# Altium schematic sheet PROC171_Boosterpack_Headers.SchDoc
size 431 x 279 mm; Date: Not shown in title block; ApprovedBy: Not shown in title block; CheckedBy: Not shown in title block; Author: Not shown in title block; CompanyName: Not shown in title block; Engineer: Not shown in title block; Organization: Not shown in title block; Address1: Not shown in title block; Address2: Not shown in title block; Address3: Not shown in title block; Address4: Not shown in title block; DocumentNumber: 21; Revision: Use project parameter SCH_Rev; SheetNumber: 21; SheetTotal: 27; PageSetup: Record=PageOptions¦CenterHorizontal=True¦CenterVertical=True¦PrintScale=1.00¦XCorrection=1.00¦YCorrection=1.00¦PrintKind=0¦BorderSize=5000000¦LeftOffset=0¦BottomOffset=0¦Orientation=2¦PaperLength=1000¦PaperWidth=1000¦Scale=100¦PaperSource=15¦PrintQuality=600¦MediaType=1¦DitherType=10¦PaperKind=Letter¦PrintScaleMode=1
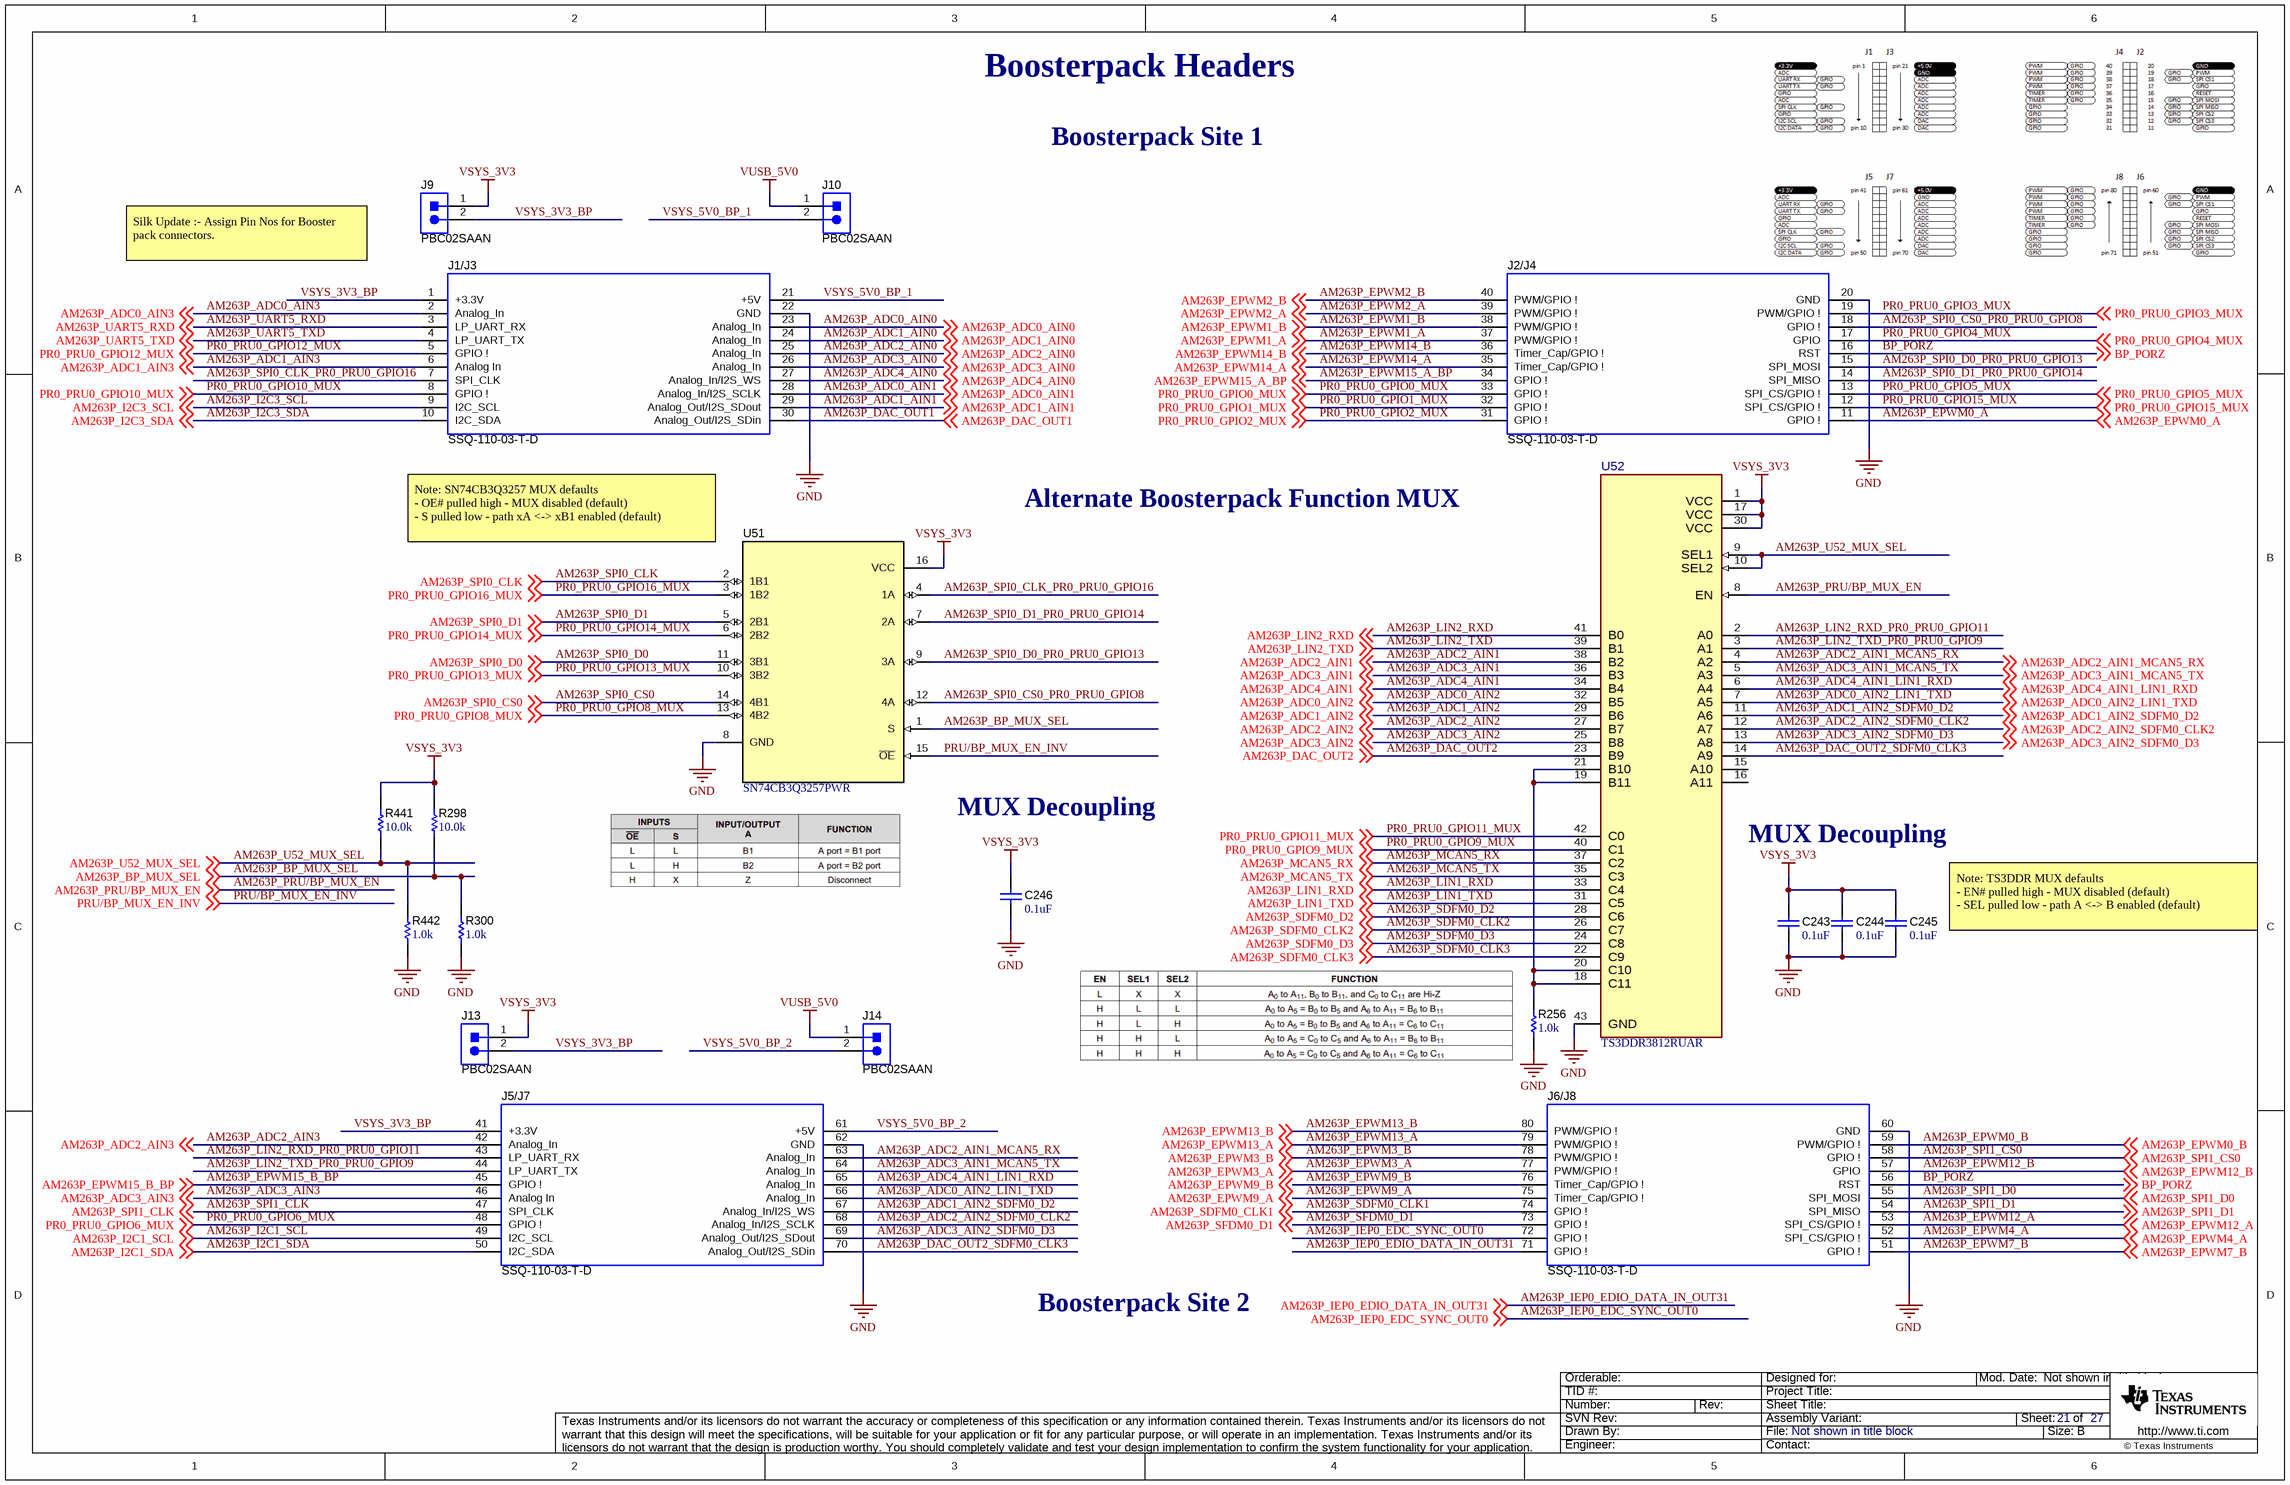
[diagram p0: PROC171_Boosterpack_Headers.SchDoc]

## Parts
C243  ValueDisplayed: 0.1uF  [0402]  (hidden comment: GRM155R71E104KE14D)
C244  ValueDisplayed: 0.1uF  [0402]  (hidden comment: GRM155R71E104KE14D)
C245  ValueDisplayed: 0.1uF  [0402]  (hidden comment: GRM155R71E104KE14D)
C246  ValueDisplayed: 0.1uF  [0402]  (hidden comment: GRM155R71E104KE14D)
J1/J3  SSQ-110-03-T-D  [BoosterPack_40pin_J1J3]
J2/J4  SSQ-110-03-T-D  [BoosterPack_40pin_J2J4]
J5/J7  SSQ-110-03-T-D  [BoosterPack_40pin_J5J7]
J6/J8  SSQ-110-03-T-D  [BoosterPack_40pin_J6J8]
J9  PBC02SAAN  [Sullins_PBC02SAAN]
J10  PBC02SAAN  [Sullins_PBC02SAAN]
J13  PBC02SAAN  [Sullins_PBC02SAAN]
J14  PBC02SAAN  [Sullins_PBC02SAAN]
R256  ValueDisplayed: 1.0k  [0402]  (hidden comment: ERJ-2GEJ102X)
R298  ValueDisplayed: 10.0k  [0402]  (hidden comment: ERJ-2RKF1002X)
R300  ValueDisplayed: 1.0k  [0402]  (hidden comment: ERJ-2GEJ102X)
R441  ValueDisplayed: 10.0k  [0402]  (hidden comment: ERJ-2RKF1002X)
R442  ValueDisplayed: 1.0k  [0402]  (hidden comment: ERJ-2GEJ102X)
U51  SN74CB3Q3257PWR  [PW0016A_L]
U52  TS3DDR3812RUAR  [RUA0042A-MFG]

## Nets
GND: C243.1 C244.1 C245.1 C246.1 J1/J3.22(GND) J2/J4.20(GND) J5/J7.62(GND) J6/J8.60(GND) R256.1 R300.1 R442.1 U51.8(GND) U52.43(GND)
VSYS_3V3: C243.2 C244.2 C245.2 C246.2 J9.1 J13.1 R298.1 R441.1 U51.16(VCC) U52.1(VCC) U52.17(VCC) U52.30(VCC)
VUSB_5V0: J10.1 J14.1
AM263P_ADC0_AIN0: J1/J3.23(Analog_In) ; off-sheet AM263P_ADC0_AIN0
AM263P_ADC0_AIN1: J1/J3.28(Analog_In/I2S_SCLK) ; off-sheet AM263P_ADC0_AIN1
AM263P_ADC0_AIN2: U52.32(B5) ; off-sheet AM263P_ADC0_AIN2
AM263P_ADC0_AIN2_LIN1_TXD: J5/J7.66(Analog_In) U52.7(A5) ; off-sheet AM263P_ADC0_AIN2_LIN1_TXD
AM263P_ADC0_AIN3: J1/J3.2(Analog_In) ; off-sheet AM263P_ADC0_AIN3
AM263P_ADC1_AIN0: J1/J3.24(Analog_In) ; off-sheet AM263P_ADC1_AIN0
AM263P_ADC1_AIN1: J1/J3.29(Analog_Out/I2S_SDout) ; off-sheet AM263P_ADC1_AIN1
AM263P_ADC1_AIN2: U52.29(B6) ; off-sheet AM263P_ADC1_AIN2
AM263P_ADC1_AIN2_SDFM0_D2: J5/J7.67(Analog_In/I2S_WS) U52.11(A6) ; off-sheet AM263P_ADC1_AIN2_SDFM0_D2
AM263P_ADC1_AIN3: J1/J3.6(Analog_In) ; off-sheet AM263P_ADC1_AIN3
AM263P_ADC2_AIN0: J1/J3.25(Analog_In) ; off-sheet AM263P_ADC2_AIN0
AM263P_ADC2_AIN1: U52.38(B2) ; off-sheet AM263P_ADC2_AIN1
AM263P_ADC2_AIN1_MCAN5_RX: J5/J7.63(Analog_In) U52.4(A2) ; off-sheet AM263P_ADC2_AIN1_MCAN5_RX
AM263P_ADC2_AIN2: U52.27(B7) ; off-sheet AM263P_ADC2_AIN2
AM263P_ADC2_AIN2_SDFM0_CLK2: J5/J7.68(Analog_In/I2S_SCLK) U52.12(A7) ; off-sheet AM263P_ADC2_AIN2_SDFM0_CLK2
AM263P_ADC2_AIN3: J5/J7.42(Analog_In) ; off-sheet AM263P_ADC2_AIN3
AM263P_ADC3_AIN0: J1/J3.26(Analog_In) ; off-sheet AM263P_ADC3_AIN0
AM263P_ADC3_AIN1: U52.36(B3) ; off-sheet AM263P_ADC3_AIN1
AM263P_ADC3_AIN1_MCAN5_TX: J5/J7.64(Analog_In) U52.5(A3) ; off-sheet AM263P_ADC3_AIN1_MCAN5_TX
AM263P_ADC3_AIN2: U52.25(B8) ; off-sheet AM263P_ADC3_AIN2
AM263P_ADC3_AIN2_SDFM0_D3: J5/J7.69(Analog_Out/I2S_SDout) U52.13(A8) ; off-sheet AM263P_ADC3_AIN2_SDFM0_D3
AM263P_ADC3_AIN3: J5/J7.46(Analog_In) ; off-sheet AM263P_ADC3_AIN3
AM263P_ADC4_AIN0: J1/J3.27(Analog_In/I2S_WS) ; off-sheet AM263P_ADC4_AIN0
AM263P_ADC4_AIN1: U52.34(B4) ; off-sheet AM263P_ADC4_AIN1
AM263P_ADC4_AIN1_LIN1_RXD: J5/J7.65(Analog_In) U52.6(A4) ; off-sheet AM263P_ADC4_AIN1_LIN1_RXD
AM263P_BP_MUX_SEL: R298.2 R300.2 U51.1(S) ; off-sheet AM263P_BP_MUX_SEL
AM263P_DAC_OUT1: J1/J3.30(Analog_Out/I2S_SDin) ; off-sheet AM263P_DAC_OUT1
AM263P_DAC_OUT2: U52.23(B9) ; off-sheet AM263P_DAC_OUT2
AM263P_DAC_OUT2_SDFM0_CLK3: J5/J7.70(Analog_Out/I2S_SDin) U52.14(A9)
AM263P_EPWM0_A: J2/J4.11(GPIO_!) ; off-sheet AM263P_EPWM0_A
AM263P_EPWM0_B: J6/J8.59(PWM/GPIO_!) ; off-sheet AM263P_EPWM0_B
AM263P_EPWM1_A: J2/J4.37(PWM/GPIO_!) ; off-sheet AM263P_EPWM1_A
AM263P_EPWM1_B: J2/J4.38(PWM/GPIO_!) ; off-sheet AM263P_EPWM1_B
AM263P_EPWM2_A: J2/J4.39(PWM/GPIO_!) ; off-sheet AM263P_EPWM2_A
AM263P_EPWM2_B: J2/J4.40(PWM/GPIO_!) ; off-sheet AM263P_EPWM2_B
AM263P_EPWM3_A: J6/J8.77(PWM/GPIO_!) ; off-sheet AM263P_EPWM3_A
AM263P_EPWM3_B: J6/J8.78(PWM/GPIO_!) ; off-sheet AM263P_EPWM3_B
AM263P_EPWM4_A: J6/J8.52(SPI_CS/GPIO_!) ; off-sheet AM263P_EPWM4_A
AM263P_EPWM7_B: J6/J8.51(GPIO_!) ; off-sheet AM263P_EPWM7_B
AM263P_EPWM9_A: J6/J8.75(Timer_Cap/GPIO_!) ; off-sheet AM263P_EPWM9_A
AM263P_EPWM9_B: J6/J8.76(Timer_Cap/GPIO_!) ; off-sheet AM263P_EPWM9_B
AM263P_EPWM12_A: J6/J8.53(SPI_CS/GPIO_!) ; off-sheet AM263P_EPWM12_A
AM263P_EPWM12_B: J6/J8.57(GPIO) ; off-sheet AM263P_EPWM12_B
AM263P_EPWM13_A: J6/J8.79(PWM/GPIO_!) ; off-sheet AM263P_EPWM13_A
AM263P_EPWM13_B: J6/J8.80(PWM/GPIO_!) ; off-sheet AM263P_EPWM13_B
AM263P_EPWM14_A: J2/J4.35(Timer_Cap/GPIO_!) ; off-sheet AM263P_EPWM14_A
AM263P_EPWM14_B: J2/J4.36(Timer_Cap/GPIO_!) ; off-sheet AM263P_EPWM14_B
AM263P_EPWM15_A_BP: J2/J4.34(GPIO_!) ; off-sheet AM263P_EPWM15_A_BP
AM263P_EPWM15_B_BP: J5/J7.45(GPIO_!) ; off-sheet AM263P_EPWM15_B_BP
AM263P_I2C1_SCL: J5/J7.49(I2C_SCL) ; off-sheet AM263P_I2C1_SCL
AM263P_I2C1_SDA: J5/J7.50(I2C_SDA) ; off-sheet AM263P_I2C1_SDA
AM263P_I2C3_SCL: J1/J3.9(I2C_SCL) ; off-sheet AM263P_I2C3_SCL
AM263P_I2C3_SDA: J1/J3.10(I2C_SDA) ; off-sheet AM263P_I2C3_SDA
AM263P_IEP0_EDC_SYNC_OUT0: J6/J8.72(GPIO_!) ; off-sheet AM263P_IEP0_EDC_SYNC_OUT0
AM263P_IEP0_EDIO_DATA_IN_OUT31: J6/J8.71(GPIO_!) ; off-sheet AM263P_IEP0_EDIO_DATA_IN_OUT31
AM263P_LIN1_RXD: U52.33(C4) ; off-sheet AM263P_LIN1_RXD
AM263P_LIN1_TXD: U52.31(C5) ; off-sheet AM263P_LIN1_TXD
AM263P_LIN2_RXD: U52.41(B0) ; off-sheet AM263P_LIN2_RXD
AM263P_LIN2_RXD_PR0_PRU0_GPIO11: J5/J7.43(LP_UART_RX) U52.2(A0)
AM263P_LIN2_TXD: U52.39(B1) ; off-sheet AM263P_LIN2_TXD
AM263P_LIN2_TXD_PR0_PRU0_GPIO9: J5/J7.44(LP_UART_TX) U52.3(A1)
AM263P_MCAN5_RX: U52.37(C2) ; off-sheet AM263P_MCAN5_RX
AM263P_MCAN5_TX: U52.35(C3) ; off-sheet AM263P_MCAN5_TX
AM263P_PRU/BP_MUX_EN: U52.8(EN) ; off-sheet AM263P_PRU/BP_MUX_EN
AM263P_SDFM0_CLK1: J6/J8.74(GPIO_!) ; off-sheet AM263P_SDFM0_CLK1
AM263P_SDFM0_CLK2: U52.26(C7) ; off-sheet AM263P_SDFM0_CLK2
AM263P_SDFM0_CLK3: U52.22(C9) ; off-sheet AM263P_SDFM0_CLK3
AM263P_SDFM0_D2: U52.28(C6) ; off-sheet AM263P_SDFM0_D2
AM263P_SDFM0_D3: U52.24(C8) ; off-sheet AM263P_SDFM0_D3
AM263P_SFDM0_D1: J6/J8.73(GPIO_!) ; off-sheet AM263P_SFDM0_D1
AM263P_SPI0_CLK: U51.2(1B1) ; off-sheet AM263P_SPI0_CLK
AM263P_SPI0_CLK_PR0_PRU0_GPIO16: J1/J3.7(SPI_CLK) U51.4(1A)
AM263P_SPI0_CS0: U51.14(4B1) ; off-sheet AM263P_SPI0_CS0
AM263P_SPI0_CS0_PR0_PRU0_GPIO8: J2/J4.18(GPIO_!) U51.12(4A)
AM263P_SPI0_D0: U51.11(3B1) ; off-sheet AM263P_SPI0_D0
AM263P_SPI0_D0_PR0_PRU0_GPIO13: J2/J4.15(SPI_MOSI) U51.9(3A)
AM263P_SPI0_D1: U51.5(2B1) ; off-sheet AM263P_SPI0_D1
AM263P_SPI0_D1_PR0_PRU0_GPIO14: J2/J4.14(SPI_MISO) U51.7(2A)
AM263P_SPI1_CLK: J5/J7.47(SPI_CLK) ; off-sheet AM263P_SPI1_CLK
AM263P_SPI1_CS0: J6/J8.58(GPIO_!) ; off-sheet AM263P_SPI1_CS0
AM263P_SPI1_D0: J6/J8.55(SPI_MOSI) ; off-sheet AM263P_SPI1_D0
AM263P_SPI1_D1: J6/J8.54(SPI_MISO) ; off-sheet AM263P_SPI1_D1
AM263P_U52_MUX_SEL: R441.2 R442.2 U52.9(SEL1) U52.10(SEL2) ; off-sheet AM263P_U52_MUX_SEL
AM263P_UART5_RXD: J1/J3.3(LP_UART_RX) ; off-sheet AM263P_UART5_RXD
AM263P_UART5_TXD: J1/J3.4(LP_UART_TX) ; off-sheet AM263P_UART5_TXD
BP_PORZ: J2/J4.16(RST) J6/J8.56(RST) ; off-sheet BP_PORZ
PR0_PRU0_GPIO0_MUX: J2/J4.33(GPIO_!) ; off-sheet PR0_PRU0_GPIO0_MUX
PR0_PRU0_GPIO1_MUX: J2/J4.32(GPIO_!) ; off-sheet PR0_PRU0_GPIO1_MUX
PR0_PRU0_GPIO2_MUX: J2/J4.31(GPIO_!) ; off-sheet PR0_PRU0_GPIO2_MUX
PR0_PRU0_GPIO3_MUX: J2/J4.19(PWM/GPIO_!) ; off-sheet PR0_PRU0_GPIO3_MUX
PR0_PRU0_GPIO4_MUX: J2/J4.17(GPIO) ; off-sheet PR0_PRU0_GPIO4_MUX
PR0_PRU0_GPIO5_MUX: J2/J4.13(SPI_CS/GPIO_!) ; off-sheet PR0_PRU0_GPIO5_MUX
PR0_PRU0_GPIO6_MUX: J5/J7.48(GPIO_!) ; off-sheet PR0_PRU0_GPIO6_MUX
PR0_PRU0_GPIO8_MUX: U51.13(4B2) ; off-sheet PR0_PRU0_GPIO8_MUX
PR0_PRU0_GPIO9_MUX: U52.40(C1) ; off-sheet PR0_PRU0_GPIO9_MUX
PR0_PRU0_GPIO10_MUX: J1/J3.8(GPIO_!) ; off-sheet PR0_PRU0_GPIO10_MUX
PR0_PRU0_GPIO11_MUX: U52.42(C0) ; off-sheet PR0_PRU0_GPIO11_MUX
PR0_PRU0_GPIO12_MUX: J1/J3.5(GPIO_!) ; off-sheet PR0_PRU0_GPIO12_MUX
PR0_PRU0_GPIO13_MUX: U51.10(3B2) ; off-sheet PR0_PRU0_GPIO13_MUX
PR0_PRU0_GPIO14_MUX: U51.6(2B2) ; off-sheet PR0_PRU0_GPIO14_MUX
PR0_PRU0_GPIO15_MUX: J2/J4.12(SPI_CS/GPIO_!) ; off-sheet PR0_PRU0_GPIO15_MUX
PR0_PRU0_GPIO16_MUX: U51.3(1B2) ; off-sheet PR0_PRU0_GPIO16_MUX
PRU/BP_MUX_EN_INV: U51.15(~{OE}) ; off-sheet PRU/BP_MUX_EN_INV
VSYS_3V3_BP: J1/J3.1(+3.3V) J5/J7.41(+3.3V) J9.2 J13.2
VSYS_5V0_BP_1: J1/J3.21(+5V) J10.2
VSYS_5V0_BP_2: J5/J7.61(+5V) J14.2
NetR256_2: R256.2 U52.18(C11) U52.19(B11) U52.20(C10) U52.21(B10)

Not connected (* = marked no-connect by the designer): U52 15(A10) 16(A11)

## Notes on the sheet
- Boosterpack Headers
- Boosterpack Site 1
- Silk Update :- Assign Pin Nos for Booster pack connectors.
- Note: SN74CB3Q3257 MUX defaults
  - OE# pulled high - MUX disabled (default)
  - S pulled low - path xA <-> xB1 enabled (default)
- Alternate Boosterpack Function MUX
- MUX Decoupling
- (near U52) MUX Decoupling
- Note: TS3DDR MUX defaults
  - EN# pulled high - MUX disabled (default)
  - SEL pulled low - path A <-> B enabled (default)
- Boosterpack Site 2

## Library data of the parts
C243-C246 = CMP-0006659-2: CAP, CERM, 0.1 uF, 25 V, +/- 10%, X7R, 0402; Manufacturer: MuRata; TaMin_C: -55°C; Polarized: N; SizeAreaWB_mm2: 3; U/M: EA; Value: 0.1uF; TaMax_C: 125°C; SizeZ_mm: 0.6; SizeX_mm: 1; SizeY_mm: 0.5; Value2: 25V; Cap_F: 100nF; AEC Category: Q200; Value1: Unknown
J1/J3 = CMP-0003837-4: Receptacle, 2.54mm, 10x2, Tin, TH; Alternate PartNumber: CRD-081413-A-G; Manufacturer: Samtec; Alternate Manufacturer: Major League Electronics; Note: Booster Pack 40 pin J1 and J3; Green_Lifecycle: Active; Green_REACh: Incomplete
J2/J4 = CMP-0078266-4: Receptacle, 2.54mm, 10x2, Tin, TH; Alternate PartNumber: CRD-081413-A-G; Manufacturer: Samtec; Alternate Manufacturer: Major League Electronics; Note: Booster Pack 40 pin J2 and J4; Green_REACh: Incomplete; Green_Lifecycle: Active
J5/J7 = CMP-0081070-3: Receptacle, 2.54mm, 10x2, Tin, TH; Alternate PartNumber: CRD-081413-A-G; Manufacturer: Samtec; Alternate Manufacturer: Major League Electronics; Note: Booster Pack 40 pin J5 and J7; Green_REACh: Incomplete; Green_Lifecycle: Active
J6/J8 = CMP-0081071-3: Receptacle, 2.54mm, 10x2, Tin, TH; Alternate PartNumber: CRD-081413-A-G; Manufacturer: Samtec; Alternate Manufacturer: Major League Electronics; Note: Booster Pack 40 pin J6 and J8; Green_REACh: Incomplete; Green_Lifecycle: Active
J9 J10 J13 J14 = CMP-0054566-1: Header, 100mil, 2x1, Gold, TH; Manufacturer: Sullins Connector Solutions; CNHeader: TRUE; Current_A: 3A; Green_Lifecycle: Active; Shrouded: N; Gender: Male; Green_REACh: Passed; Voltage_V: 1.8kV; Row_Count: 1; Pitch_mm: 2.54; CT: FALSE; Cert_UL: Y
R256 R300 R442 = CMP-0078193-1: RES, 1.0 k, 5%, 0.1 W, AEC-Q200 Grade 0, 0402; Manufacturer: Panasonic; Value_Code: 1k00; SizeArea_mm2: 0.5; AEC Qualified: Y; AEC Category: Q200; Res_ohm: 1k; Value: 1.0k; SizeZ_mm: 0.6; Green_REACh: Passed; EIA_Code: E24; TempCo: 200 ppm/C; AEC Grade: 0; Power_W: 100mW; VDC_V: 50V; Value2: 0.1W; Green_Lifecycle: Active; U/M: EA; SizeX_mm: 1
R298 R441 = CMP-0026658-1: RES, 10.0 k, 1%, 0.1 W, 0402; Manufacturer: Panasonic; Power_W: 100mW; TempCo: 100 ppm/C; Value_Code: 10k0; U/M: EA; Value: 10.0k; EIA_Code: E96; Res_ohm: 10k; SizeX_mm: 1; SizeY_mm: 0.5; SizeZ_mm: 0.6; Value2: 0.1W; VDC_V: 50V; AEC Category: Q200
U51 = CMP-0076540-1: 4-Bit One-of-2 FET Multiplexer/Demultiplexer 2.5-V/3.3-V Low-Voltage, High-Bandwidth Bus Switch, PW0016A (TSSOP-16); Manufacturer: Texas Instruments; SizeAreaWB_mm2: 58.8; SizeArea_mm2: 32.0; SizeZ_mm: 1.2; SizeY_mm: 5.0; U/M: EA; CompType: IC; SizeX_mm: 6.4
U52 = CMP-0093539-2: IC MUX/DEMUX DDR3 1:2 42WQFN; Manufacturer: Texas Instruments; TaMax_C: +85°C; TaMin_C: -40°C; On State Resistance: 8Ω; SizeZ_mm: 0.8mm; Min Supply Voltage: 3V; Standoff Height: 0mm; Max Supply Voltage: 3.6V; AEC Qualified: No; PositionCount: 12; -3Db Bandwith: 1.675GHz; Nominal Supply Current: 300uA; AEC Category: Q200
